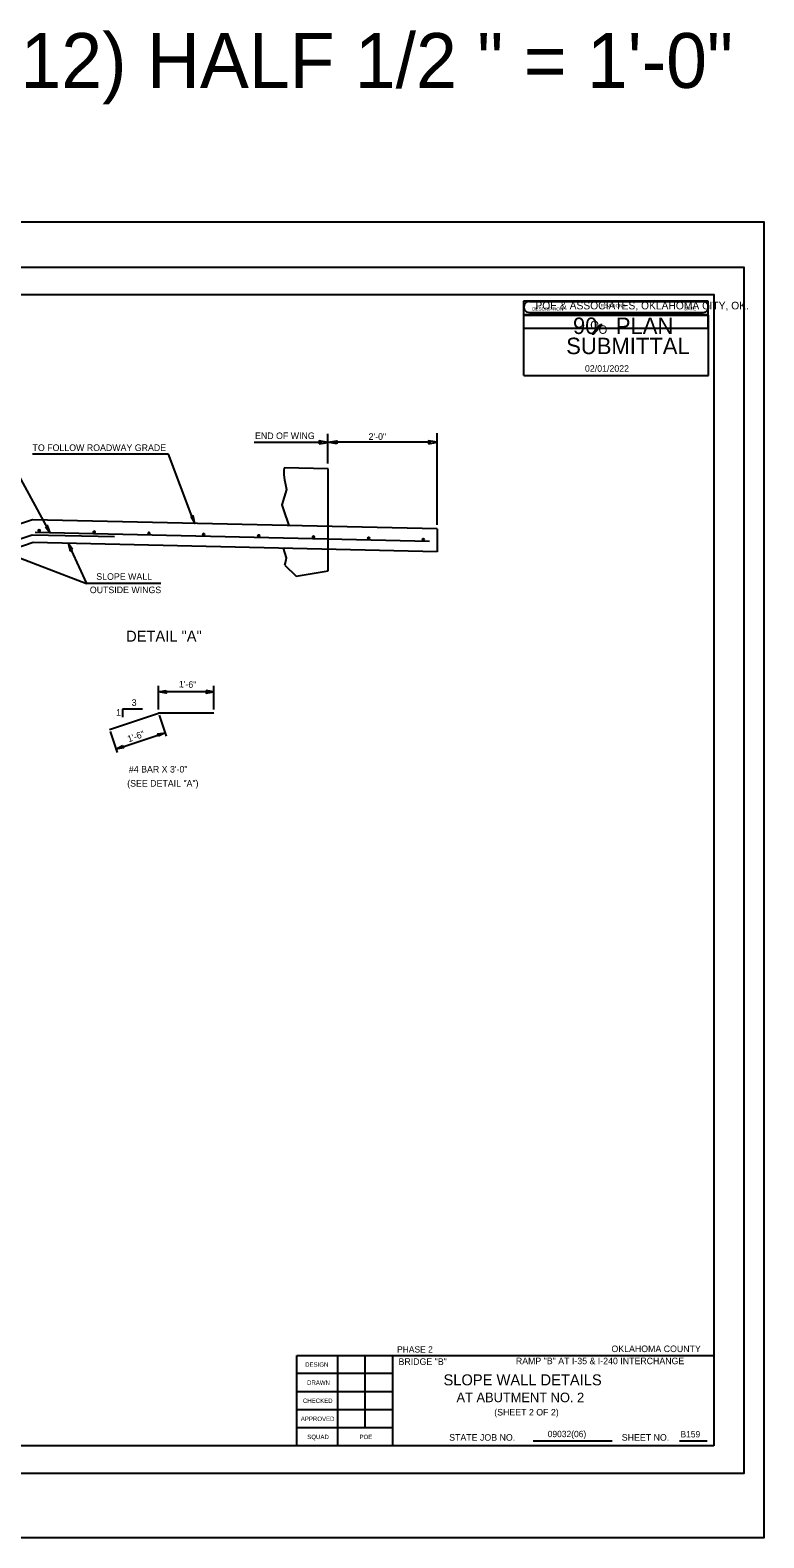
# Model space of a CAD drawing. Extents: x 570 to 2152770, y 726 to 139926.
# Drawn here: x 2152533.11 to 2152546.48, y 139374.83 to 139402.33 of the extents above; entities that cross this region are included whole.
import ezdxf

# ---------------------------------------------------------------- set-up
doc = ezdxf.new("R2010")
doc.units = 0
for name, color, linetype in [('4', 7, 'Continuous'), ('9', 7, 'Continuous'), ('Default', 7, 'Continuous'), ('PR_Bridge_Prof', 7, 'Continuous'), ('PR_Dimensions', 7, 'Continuous'), ('PR_JOINT', 7, 'Continuous'), ('PR_Reinforcing', 7, 'Continuous'), ('PR_SlopeWall', 7, 'Continuous'), ('S', 7, 'Continuous'), ('SHT_Plot_Shape_Full', 7, 'Continuous'), ('SHT_Plot_Shape_Half', 7, 'Continuous'), ('SHT_Sheet_Border', 7, 'Continuous'), ('SHT_Stamp_90_Submit', 7, 'Continuous'), ('SHT_Stamp_Rev_Block', 7, 'Continuous'), ('SHT_Standard_Sheet_Lines', 7, 'Continuous'), ('SHT_Standard_Sheet_Txt', 7, 'Continuous'), ('T', 7, 'Continuous'), ('T-Subtitle', 7, 'Continuous'), ('T-Title', 7, 'Continuous')]:
    doc.layers.add(name, color=color, linetype=linetype)

# ---------------------------------------------------------------- blocks, each defined once
blk = doc.blocks.new('ARROWHD_15')
at = {"layer": 'Default'}
blk.add_lwpolyline([(0.0261, -0.0045), (0.0261, 0.0043), (-0.0004, -0.0001)], close=True, dxfattribs=at)

msp = doc.modelspace()

# ---------------------------------------------------------------- linework, layer by layer
at = {"layer": '4'}
for p in [(2152534.552, 139389.573), (2152536.454, 139389.871)]:
    msp.add_line(p, (2152535.445, 139389.871), dxfattribs=at)
at = {"layer": '9'}
for start, end in [(356.6255, 176.6255), (176.6255, 356.6255)]:
    msp.add_arc((2152533.272, 139393.199), 0.0143, start, end, dxfattribs=at)
at = {"layer": 'PR_Bridge_Prof'}
for p, q in [((2152538.538, 139394.324), (2152537.734, 139394.342)), ((2152538.538, 139392.465), (2152538.538, 139394.324)), ((2152537.751, 139392.567), (2152537.954, 139392.37)), ((2152537.954, 139392.37), (2152538.538, 139392.465))]:
    msp.add_line(p, q, dxfattribs=at)
at = {"layer": 'PR_Dimensions'}
for p, q in [((2152538.423, 139394.808), (2152537.189, 139394.808)), ((2152538.535, 139394.422), (2152538.535, 139394.966)), ((2152540.413, 139394.809), (2152538.588, 139394.809)), ((2152540.527, 139393.307), (2152540.527, 139394.975)), ((2152535.628, 139394.591), (2152533.15, 139394.591)), ((2152535.487, 139392.235), (2152534.135, 139392.235)), ((2152535.445, 139389.938), (2152535.445, 139390.367)), ((2152536.454, 139389.938), (2152536.454, 139390.367)), ((2152536.454, 139390.259), (2152535.445, 139390.259)), ((2152535.154, 139389.94), (2152534.788, 139389.94)), ((2152534.788, 139389.94), (2152534.788, 139389.795)), ((2152535.458, 139389.832), (2152535.586, 139389.448)), ((2152534.565, 139389.534), (2152534.693, 139389.15)), ((2152534.671, 139389.214), (2152535.565, 139389.512))]:
    msp.add_line(p, q, dxfattribs=at)
for points in [[(2152538.375, 139394.781), (2152538.535, 139394.808), (2152538.375, 139394.835)], [(2152538.694, 139394.782), (2152538.534, 139394.809), (2152538.694, 139394.835)], [(2152540.365, 139394.783), (2152540.525, 139394.809), (2152540.365, 139394.836)], [(2152536.035, 139393.453), (2152536.107, 139393.331), (2152536.079, 139393.47)], [(2152533.385, 139393.269), (2152533.472, 139393.157), (2152533.426, 139393.292)], [(2152533.877, 139392.852), (2152533.798, 139392.969), (2152533.835, 139392.832)], [(2152535.584, 139390.282), (2152535.584, 139390.237), (2152535.449, 139390.259)], [(2152536.316, 139390.282), (2152536.316, 139390.237), (2152536.45, 139390.259)]]:
    msp.add_lwpolyline(points, close=True, dxfattribs=at)
for points in [[(2152536.057, 139393.461), (2152535.628, 139394.591)], [(2152533.472, 139393.157), (2152532.903, 139394.211)], [(2152532.647, 139392.808), (2152534.135, 139392.235)], [(2152533.856, 139392.842), (2152534.135, 139392.235)]]:
    msp.add_lwpolyline(points, dxfattribs=at)
at = {"layer": 'PR_JOINT'}
for points in [[(2152537.734, 139394.342), (2152537.73, 139394.296), (2152537.733, 139394.213), (2152537.743, 139394.127), (2152537.759, 139394.038), (2152537.779, 139393.949), (2152537.697, 139393.666), (2152537.724, 139393.578), (2152537.821, 139393.294)], [(2152537.751, 139392.567), (2152537.759, 139392.611), (2152537.779, 139392.701), (2152537.727, 139392.879)]]:
    msp.add_lwpolyline(points, dxfattribs=at)
at = {"layer": 'PR_Reinforcing'}
for p, q in [((2152533.144, 139393.118), (2152531.722, 139392.639)), ((2152534.644, 139393.084), (2152533.144, 139393.118)), ((2152540.384, 139393.002), (2152533.199, 139393.164))]:
    msp.add_line(p, q, dxfattribs=at)
for centre in [(2152533.272, 139393.2), (2152534.275, 139393.172), (2152535.272, 139393.151), (2152536.271, 139393.128), (2152537.274, 139393.104), (2152538.271, 139393.081), (2152539.275, 139393.061), (2152540.273, 139393.036)]:
    msp.add_circle(centre, 0.0143, dxfattribs=at)
for centre, start, end in [((2152534.275, 139393.172), 356.6255, 176.6255), ((2152534.275, 139393.172), 176.6255, 356.6255), ((2152535.272, 139393.151), 356.6255, 176.6255), ((2152535.272, 139393.151), 176.6255, 356.6255), ((2152536.271, 139393.129), 356.6255, 176.6255), ((2152536.271, 139393.129), 176.6255, 356.6255), ((2152537.274, 139393.104), 356.6255, 176.6255), ((2152537.274, 139393.104), 176.6255, 356.6255), ((2152538.271, 139393.081), 356.6255, 176.6255), ((2152538.271, 139393.081), 176.6255, 356.6255), ((2152539.276, 139393.061), 356.6255, 176.6255), ((2152539.276, 139393.061), 176.6255, 356.6255), ((2152540.273, 139393.036), 176.6255, 356.6255), ((2152540.273, 139393.036), 356.6255, 176.6255)]:
    msp.add_arc(centre, 0.0143, start, end, dxfattribs=at)
at = {"layer": 'PR_SlopeWall'}
for p, q in [((2152533.151, 139393.396), (2152531.121, 139392.72)), ((2152540.528, 139393.231), (2152533.153, 139393.397)), ((2152540.528, 139393.231), (2152540.528, 139392.814)), ((2152533.164, 139392.98), (2152531.22, 139392.332)), ((2152540.528, 139392.814), (2152533.164, 139392.98))]:
    msp.add_line(p, q, dxfattribs=at)
at = {"layer": 'SHT_Plot_Shape_Full'}
msp.add_lwpolyline([(2152510.479, 139398.83), (2152546.479, 139398.83), (2152546.479, 139374.83), (2152510.479, 139374.83)], close=True, dxfattribs=at)
at = {"layer": 'SHT_Plot_Shape_Half'}
msp.add_lwpolyline([(2152512.116, 139398.005), (2152546.116, 139398.005), (2152546.116, 139376.005), (2152512.116, 139376.005)], close=True, dxfattribs=at)
at = {"layer": 'SHT_Sheet_Border'}
for p, q in [((2152537.966, 139376.505), (2152537.966, 139378.155)), ((2152537.966, 139378.155), (2152545.566, 139378.155)), ((2152539.716, 139376.505), (2152539.716, 139378.155))]:
    msp.add_line(p, q, dxfattribs=at)
msp.add_lwpolyline([(2152545.566, 139376.505), (2152514.066, 139376.505), (2152514.066, 139397.505), (2152545.566, 139397.505)], close=True, dxfattribs=at)
at = {"layer": 'SHT_Stamp_90_Submit'}
for p, q in [((2152542.206, 139397.376), (2152545.372, 139397.376)), ((2152542.106, 139397.126), (2152545.472, 139397.126)), ((2152542.106, 139396.026), (2152542.106, 139397.126)), ((2152542.206, 139397.176), (2152545.372, 139397.176)), ((2152543.349, 139396.787), (2152543.505, 139396.96)), ((2152543.367, 139396.787), (2152543.523, 139396.96)), ((2152543.372, 139396.787), (2152543.528, 139396.96)), ((2152543.38, 139396.787), (2152543.535, 139396.96)), ((2152543.505, 139396.96), (2152543.535, 139396.96)), ((2152545.472, 139396.026), (2152545.472, 139397.126)), ((2152543.349, 139396.787), (2152543.38, 139396.787)), ((2152542.106, 139396.026), (2152545.472, 139396.026))]:
    msp.add_line(p, q, dxfattribs=at)
for centre, start, end in [((2152542.206, 139397.276), 89.9952, 270), ((2152545.372, 139397.276), 270, 90.0048)]:
    msp.add_arc(centre, 0.1, start, end, dxfattribs=at)
at = {"layer": 'SHT_Stamp_Rev_Block'}
for p, q in [((2152542.097, 139397.384), (2152542.097, 139396.884)), ((2152545.463, 139397.384), (2152542.097, 139397.384)), ((2152545.463, 139396.884), (2152545.463, 139397.384)), ((2152545.463, 139397.134), (2152542.097, 139397.134)), ((2152545.463, 139396.884), (2152542.097, 139396.884))]:
    msp.add_line(p, q, dxfattribs=at)
at = {"layer": 'SHT_Standard_Sheet_Lines'}
for p, q in [((2152538.716, 139376.505), (2152538.716, 139378.155)), ((2152539.216, 139376.835), (2152539.216, 139378.155)), ((2152542.277, 139376.601), (2152543.717, 139376.601)), ((2152544.942, 139376.601), (2152545.444, 139376.601))]:
    msp.add_line(p, q, dxfattribs=at)
for points in [[(2152539.716, 139377.825), (2152537.966, 139377.825)], [(2152539.716, 139377.495), (2152537.966, 139377.495)], [(2152539.716, 139377.165), (2152537.966, 139377.165)], [(2152539.716, 139376.835), (2152537.966, 139376.835)]]:
    msp.add_lwpolyline(points, dxfattribs=at)

# ---------------------------------------------------------------- block references
at = {"layer": 'PR_Dimensions'}
for p, xscale, yscale, rotation in [((2152535.565, 139389.512), 5.094669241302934, -5.094669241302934, -161.5742061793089), ((2152534.674, 139389.214), 5.094669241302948, -5.094669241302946, 18.4257938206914)]:
    msp.add_blockref('ARROWHD_15', p, dxfattribs=dict(at, xscale=xscale, yscale=yscale, rotation=rotation))

# ---------------------------------------------------------------- texts
at = {"layer": 'S'}
msp.add_text('SCALE:  FULL 1" = 1\'-0" (SF=12) HALF 1/2 " = 1\'-0"', height=1.00003, dxfattribs=at).set_placement((2152515.078, 139401.272))
at = {"layer": 'SHT_Stamp_90_Submit'}
for s, height, p in [('POE & ASSOCIATES, OKLAHOMA CITY, OK.', 0.14, (2152542.316, 139397.233)), ('90   PLAN', 0.3, (2152543.001, 139396.784)), ('O', 0.153, (2152543.315, 139396.872)), ('O', 0.153, (2152543.467, 139396.788)), ('SUBMITTAL', 0.3, (2152542.877, 139396.417)), ('02/01/2022', 0.12, (2152543.219, 139396.095))]:
    msp.add_text(s, height=height, dxfattribs=at).set_placement(p)
at = {"layer": 'SHT_Stamp_Rev_Block'}
for s, p in [('DESCRIPTION', (2152542.257, 139397.212)), ('REVISIONS', (2152543.505, 139397.271)), ('DATE', (2152545.027, 139397.216))]:
    msp.add_text(s, height=0.06, dxfattribs=at).set_placement(p)
at = {"layer": 'SHT_Standard_Sheet_Txt'}
for s, height, p in [('DESIGN', 0.08, (2152538.119, 139377.95)), ('DRAWN', 0.08, (2152538.154, 139377.62)), ('CHECKED', 0.08, (2152538.079, 139377.29)), ('APPROVED', 0.08, (2152538.04, 139376.96)), ('SQUAD', 0.08, (2152538.158, 139376.63)), ('POE', 0.08, (2152539.111, 139376.63)), ('STATE JOB NO.', 0.12, (2152540.744, 139376.601)), ('SHEET NO. ', 0.12, (2152543.89, 139376.601))]:
    msp.add_text(s, height=height, dxfattribs=at).set_placement(p)
at = {"layer": 'T'}
for s, height, p in [('TO FOLLOW ROADWAY GRADE', 0.12, (2152533.151, 139394.651)), ('END OF WING', 0.12, (2152537.206, 139394.868)), ('2\'-0"', 0.12, (2152539.275, 139394.854)), ('SLOPE WALL', 0.12, (2152534.313, 139392.301)), ('OUTSIDE WINGS', 0.12, (2152534.195, 139392.058)), ('3', 0.12, (2152534.958, 139390.003)), ('1', 0.12, (2152534.675, 139389.823)), ('#4 BAR X 3\'-0"', 0.12, (2152534.907, 139388.787)), ('(SEE DETAIL "A")', 0.12, (2152534.876, 139388.529)), ('PHASE 2', 0.1152, (2152539.795, 139378.209)), ('OKLAHOMA COUNTY', 0.11979, (2152543.702, 139378.217)), ('BRIDGE "B" ', 0.12, (2152539.821, 139377.983)), ('RAMP "B" AT I-35 & I-240 INTERCHANGE', 0.11979, (2152541.96, 139377.996)), ('(SHEET 2 OF 2)', 0.11979, (2152541.566, 139377.061)), ('09032(06)', 0.1152, (2152542.54, 139376.666)), ('B159', 0.1152, (2152544.96, 139376.661))]:
    msp.add_text(s, height=height, dxfattribs=at).set_placement(p)
for rotation, p in [(358.4323, (2152535.816, 139390.339)), (19.1967, (2152534.904, 139389.337))]:
    msp.add_text('1\'-6"', height=0.12, rotation=rotation, dxfattribs=at).set_placement(p)
at = {"layer": 'T-Subtitle'}
msp.add_text('AT ABUTMENT NO. 2', height=0.175, dxfattribs=at).set_placement((2152540.878, 139377.303))
at = {"layer": 'T-Title'}
for s, p in [('DETAIL "A"', (2152534.856, 139391.173)), ('SLOPE WALL DETAILS', (2152540.641, 139377.611))]:
    msp.add_text(s, height=0.2, dxfattribs=at).set_placement(p)

doc.saveas('drawing.dxf')
